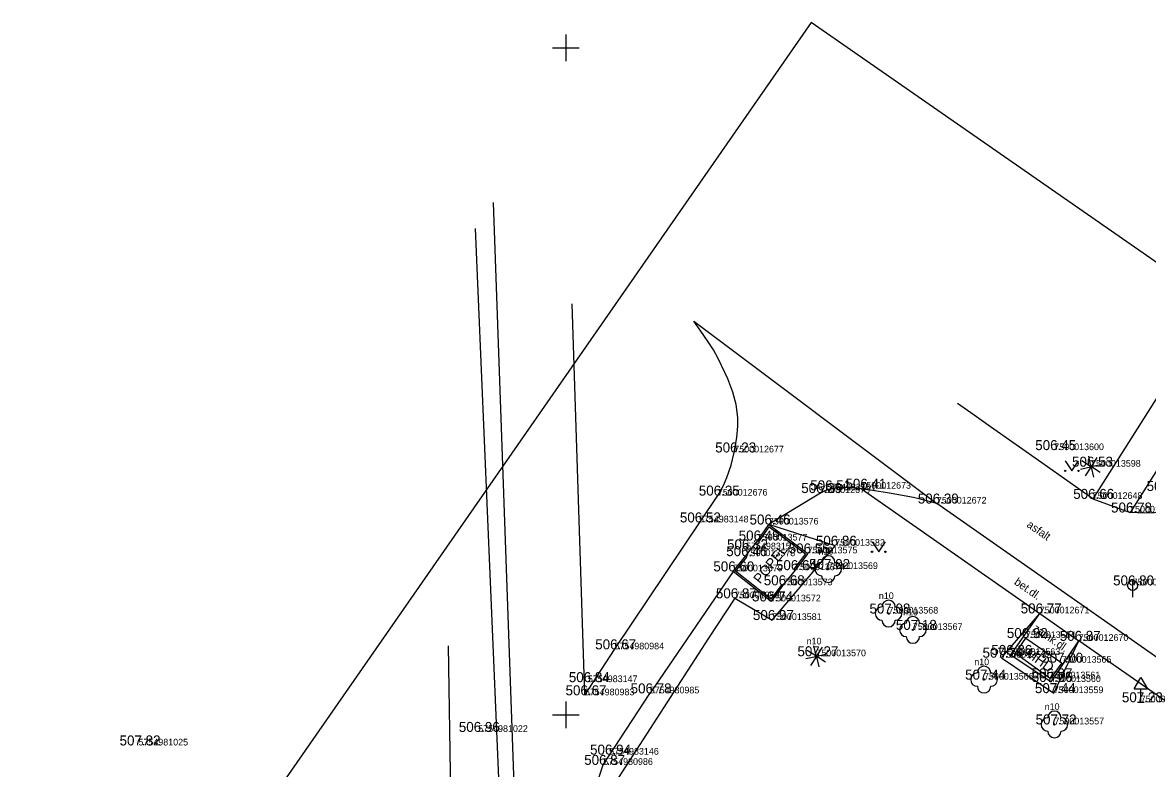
# Model space of a CAD drawing. Extents: x -669251 to -668549, y -1128351 to -1127698.
# Drawn here: x -669040.7 to -668956.4, y -1127754 to -1127698.1 of the extents above; entities that cross this region are included whole.
import ezdxf

# ---------------------------------------------------------------- set-up
doc = ezdxf.new("R2010")
doc.units = 0
for name, color, linetype in [('Vrstva 1', 7, 'Continuous'), ('Vrstva 10', 7, 'Continuous'), ('Vrstva 11', 7, 'Continuous'), ('Vrstva 14', 7, 'Continuous'), ('Vrstva 2', 7, 'Continuous'), ('Vrstva 22', 7, 'Continuous'), ('Vrstva 27', 7, 'Continuous'), ('Vrstva 3', 7, 'Continuous'), ('Vrstva 34', 7, 'Continuous'), ('Vrstva 36', 7, 'Continuous'), ('Vrstva 40', 7, 'Continuous'), ('Vrstva 42', 7, 'Continuous'), ('Vrstva 47', 7, 'Continuous'), ('Vrstva 5', 7, 'Continuous'), ('Vrstva 60', 7, 'Continuous'), ('Vrstva 61', 7, 'Continuous'), ('Vrstva 7', 7, 'Continuous')]:
    doc.layers.add(name, color=color, linetype=linetype)

msp = doc.modelspace()

# ---------------------------------------------------------------- linework, layer by layer
at = {"layer": 'Vrstva 1'}
for p, q in [((-668987.371, -1127730.338), (-668987.371, -1127730.338)), ((-668963.378, -1127730.163), (-668963.378, -1127730.163)), ((-668960.621, -1127731.406), (-668960.621, -1127731.406)), ((-668980.919, -1127733.381), (-668980.919, -1127733.381)), ((-668980.484, -1127733.176), (-668980.484, -1127733.176)), ((-668977.843, -1127733.058), (-668977.843, -1127733.058)), ((-668988.6, -1127733.573), (-668988.6, -1127733.573)), ((-668972.179, -1127734.169), (-668972.179, -1127734.169)), ((-668960.495, -1127733.821), (-668960.495, -1127733.821)), ((-668957.695, -1127734.841), (-668957.695, -1127734.841)), ((-668990.019, -1127735.584), (-668990.019, -1127735.584)), ((-668984.772, -1127735.741), (-668984.772, -1127735.741)), ((-668986.484, -1127737.608), (-668986.484, -1127737.608)), ((-668985.608, -1127736.94), (-668985.608, -1127736.94)), ((-668979.801, -1127737.333), (-668979.801, -1127737.333)), ((-668986.519, -1127738.114), (-668986.519, -1127738.114)), ((-668981.859, -1127737.906), (-668981.859, -1127737.906)), ((-668987.461, -1127739.256), (-668987.461, -1127739.256)), ((-668982.804, -1127739.163), (-668982.804, -1127739.163)), ((-668980.324, -1127739.079), (-668980.324, -1127739.079)), ((-668983.718, -1127740.297), (-668983.718, -1127740.297)), ((-668957.506, -1127740.307), (-668957.506, -1127740.307)), ((-668987.321, -1127741.273), (-668987.321, -1127741.273)), ((-668984.608, -1127741.507), (-668984.608, -1127741.507)), ((-668975.801, -1127742.415), (-668975.801, -1127742.415)), ((-668964.469, -1127742.407), (-668964.469, -1127742.407)), ((-668984.541, -1127742.903), (-668984.541, -1127742.903)), ((-668973.983, -1127743.642), (-668973.983, -1127743.642)), ((-668965.506, -1127744.254), (-668965.506, -1127744.254)), ((-668996.352, -1127745.1), (-668996.352, -1127745.1)), ((-668961.545, -1127744.464), (-668961.545, -1127744.464)), ((-668981.218, -1127745.619), (-668981.218, -1127745.619)), ((-668967.345, -1127745.727), (-668967.345, -1127745.727)), ((-668966.649, -1127745.52), (-668966.649, -1127745.52)), ((-668962.815, -1127746.103), (-668962.815, -1127746.103)), ((-668998.345, -1127747.56), (-668998.345, -1127747.56)), ((-668968.649, -1127747.373), (-668968.649, -1127747.373)), ((-668963.652, -1127747.276), (-668963.652, -1127747.276)), ((-668963.608, -1127747.547), (-668963.608, -1127747.547)), ((-668998.578, -1127748.546), (-668998.578, -1127748.546)), ((-668993.711, -1127748.403), (-668993.711, -1127748.403)), ((-668963.417, -1127748.384), (-668963.417, -1127748.384)), ((-668956.897, -1127749.069), (-668956.897, -1127749.069)), ((-668963.367, -1127750.731), (-668963.367, -1127750.731)), ((-669006.566, -1127751.293), (-669006.566, -1127751.293)), ((-669032.037, -1127752.307), (-669032.037, -1127752.307)), ((-668996.75, -1127752.993), (-668996.75, -1127752.993)), ((-668997.193, -1127753.764), (-668997.193, -1127753.764))]:
    msp.add_line(p, q, dxfattribs=at)
at = {"layer": 'Vrstva 10'}
for p, q in [((-669003.824, -1127756.515), (-669005.418, -1127711.59)), ((-668947.975, -1127714.013), (-668960.495, -1127733.821)), ((-668946.997, -1127717.845), (-668957.695, -1127734.841)), ((-668998.578, -1127748.546), (-668999.53, -1127719.204)), ((-668977.843, -1127733.058), (-668964.469, -1127742.407)), ((-668986.519, -1127738.114), (-668985.608, -1127736.94)), ((-668987.461, -1127739.256), (-668993.711, -1127748.403)), ((-668982.804, -1127739.163), (-668983.718, -1127740.297)), ((-668966.649, -1127745.52), (-668964.469, -1127742.407)), ((-668998.578, -1127748.546), (-668996.352, -1127745.1)), ((-668963.608, -1127747.547), (-668961.545, -1127744.464)), ((-668934.08, -1127763.578), (-668961.545, -1127744.464)), ((-668966.649, -1127745.52), (-668963.608, -1127747.547)), ((-668997.193, -1127753.764), (-668993.711, -1127748.403)), ((-668997.972, -1127756.059), (-668997.193, -1127753.764))]:
    msp.add_line(p, q, dxfattribs=at)
for points in [[(-668996.352, -1127745.1), (-668992.476, -1127739.336), (-668988.6, -1127733.573), (-668988.174, -1127732.821), (-668987.919, -1127732.22), (-668987.615, -1127731.285), (-668987.371, -1127730.338), (-668987.169, -1127729.22), (-668987.105, -1127728.36), (-668987.113, -1127727.713), (-668987.227, -1127726.753), (-668987.476, -1127725.824), (-668987.862, -1127724.813), (-668988.543, -1127723.35), (-668988.938, -1127722.65), (-668989.374, -1127721.974), (-668989.884, -1127721.236), (-668990.394, -1127720.498)], [(-668943.828, -1127723.016), (-668947.216, -1127727.392), (-668950.604, -1127731.768), (-668951.311, -1127732.58), (-668951.902, -1127733.131), (-668952.38, -1127733.508), (-668953.156, -1127734.01), (-668954.004, -1127734.43), (-668954.644, -1127734.658), (-668955.127, -1127734.774), (-668955.856, -1127734.87), (-668956.592, -1127734.881), (-668957.144, -1127734.861), (-668957.695, -1127734.841)], [(-668960.495, -1127733.821), (-668964.324, -1127731.119), (-668968.152, -1127728.415), (-668969.393, -1127727.536), (-668970.634, -1127726.657)], [(-668972.179, -1127734.169), (-668972.659, -1127734.039), (-668973.942, -1127733.727), (-668975.89, -1127733.357), (-668977.843, -1127733.058), (-668978.628, -1127732.971), (-668979.231, -1127732.955), (-668979.68, -1127732.984), (-668980.327, -1127733.116), (-668980.631, -1127733.23), (-668980.919, -1127733.381), (-668982.846, -1127734.561), (-668984.772, -1127735.741)], [(-668947.059, -1127751.764), (-668959.619, -1127742.966), (-668972.179, -1127734.169)]]:
    msp.add_lwpolyline(points, dxfattribs=at)
at = {"layer": 'Vrstva 11'}
for p, q in [((-668990.394, -1127720.498), (-668972.179, -1127734.169)), ((-668960.495, -1127733.821), (-668957.695, -1127734.841)), ((-668964.469, -1127742.407), (-668961.545, -1127744.464))]:
    msp.add_line(p, q, dxfattribs=at)
at = {"layer": 'Vrstva 14'}
for p, q in [((-669006.806, -1127713.552), (-669004.988, -1127756.361)), ((-668979.801, -1127737.333), (-668984.772, -1127735.741)), ((-668984.541, -1127742.903), (-668979.801, -1127737.333)), ((-668987.321, -1127741.273), (-668989.294, -1127744.271)), ((-668987.321, -1127741.273), (-668984.541, -1127742.903)), ((-668967.345, -1127745.727), (-668964.469, -1127742.407)), ((-668989.294, -1127744.271), (-668996.266, -1127755.056)), ((-669008.429, -1127768.237), (-669008.802, -1127744.83)), ((-668963.417, -1127748.384), (-668961.545, -1127744.464)), ((-668967.345, -1127745.727), (-668963.417, -1127748.384))]:
    msp.add_line(p, q, dxfattribs=at)
at = {"layer": 'Vrstva 22'}
for p, q in [((-668960.629, -1127731.366), (-668960.801, -1127730.612)), ((-668960.187, -1127730.716), (-668960.601, -1127731.372)), ((-668961.415, -1127731.586), (-668960.661, -1127731.414)), ((-668960.655, -1127731.386), (-668961.311, -1127730.972)), ((-668960.641, -1127731.44), (-668961.055, -1127732.096)), ((-668960.613, -1127731.446), (-668960.441, -1127732.2)), ((-668959.931, -1127731.84), (-668960.587, -1127731.426)), ((-668960.581, -1127731.398), (-668959.827, -1127731.226)), ((-668981.252, -1127745.599), (-668981.908, -1127745.185)), ((-668981.226, -1127745.579), (-668981.398, -1127744.825)), ((-668980.784, -1127744.929), (-668981.198, -1127745.585)), ((-668982.012, -1127745.799), (-668981.258, -1127745.627)), ((-668981.238, -1127745.653), (-668981.652, -1127746.309)), ((-668981.21, -1127745.659), (-668981.038, -1127746.413)), ((-668980.528, -1127746.053), (-668981.184, -1127745.639)), ((-668981.178, -1127745.611), (-668980.424, -1127745.439))]:
    msp.add_line(p, q, dxfattribs=at)
for centre, radius in [((-668960.621, -1127731.406), 0.04), ((-668980.324, -1127739.079), 0.05), ((-668975.801, -1127742.415), 0.05), ((-668973.983, -1127743.642), 0.05), ((-668981.218, -1127745.619), 0.04), ((-668968.649, -1127747.373), 0.05), ((-668963.367, -1127750.731), 0.05)]:
    msp.add_circle(centre, radius, dxfattribs=at)
for centre, start, end in [((-668980.324, -1127738.579), 0, 180), ((-668980.824, -1127739.079), 90, 270), ((-668979.824, -1127739.079), 270, 90), ((-668980.324, -1127739.579), 180, 0), ((-668975.801, -1127741.915), 0, 180), ((-668976.301, -1127742.415), 90, 270), ((-668975.301, -1127742.415), 270, 90), ((-668973.983, -1127743.142), 0, 180), ((-668975.801, -1127742.915), 180, 0), ((-668974.483, -1127743.642), 90, 270), ((-668973.483, -1127743.642), 270, 90), ((-668973.983, -1127744.142), 180, 0), ((-668969.149, -1127747.373), 90, 270), ((-668968.649, -1127746.873), 0, 180), ((-668968.149, -1127747.373), 270, 90), ((-668968.649, -1127747.873), 180, 0), ((-668963.867, -1127750.731), 90, 270), ((-668963.367, -1127750.231), 0, 180), ((-668962.867, -1127750.731), 270, 90), ((-668963.367, -1127751.231), 180, 0)]:
    msp.add_arc(centre, 0.5, start, end, dxfattribs=at)
at = {"layer": 'Vrstva 27'}
msp.add_line((-668957.506, -1127739.932), (-668957.506, -1127741.182), dxfattribs=at)
msp.add_circle((-668957.506, -1127740.307), 0.375, dxfattribs=at)
at = {"layer": 'Vrstva 34'}
for p, q in [((-668957.397, -1127748.069), (-668956.897, -1127747.219)), ((-668956.897, -1127747.219), (-668956.397, -1127748.069)), ((-668957.397, -1127748.069), (-668956.397, -1127748.069)), ((-668956.897, -1127749.069), (-668956.897, -1127748.069)), ((-668957.147, -1127749.069), (-668956.647, -1127749.069))]:
    msp.add_line(p, q, dxfattribs=at)
at = {"layer": 'Vrstva 36'}
for p, q in [((-668962.564, -1127730.974), (-668962.064, -1127731.724)), ((-668962.064, -1127731.724), (-668961.564, -1127730.974)), ((-668977.041, -1127737.033), (-668976.541, -1127737.783)), ((-668976.541, -1127737.783), (-668976.041, -1127737.033))]:
    msp.add_line(p, q, dxfattribs=at)
for centre in [(-668962.566, -1127731.724), (-668961.566, -1127731.724), (-668977.041, -1127737.783), (-668976.041, -1127737.783)]:
    msp.add_circle(centre, 0.05, dxfattribs=at)
at = {"layer": 'Vrstva 5'}
for p, q in [((-668966.289, -1127745.394), (-668965.506, -1127744.254)), ((-668965.506, -1127744.254), (-668962.815, -1127746.103)), ((-668966.289, -1127745.394), (-668963.652, -1127747.276)), ((-668962.815, -1127746.103), (-668963.652, -1127747.276))]:
    msp.add_line(p, q, dxfattribs=at)
at = {"layer": 'Vrstva 60'}
msp.add_lwpolyline([(-668982.815, -1128190.464), (-668751.689, -1127857.889), (-668981.618, -1127698.099), (-669212.743, -1128030.674)], close=True, dxfattribs=at)
at = {"layer": 'Vrstva 61'}
for p, q in [((-669000, -1127699), (-669000, -1127701)), ((-669001, -1127700), (-668999, -1127700)), ((-669000, -1127749), (-669000, -1127751)), ((-669001, -1127750), (-668999, -1127750))]:
    msp.add_line(p, q, dxfattribs=at)
at = {"layer": 'Vrstva 7'}
for p, q in [((-668985.608, -1127736.94), (-668984.772, -1127735.741)), ((-668985.51, -1127737.009), (-668984.744, -1127735.911)), ((-668984.772, -1127735.741), (-668981.859, -1127737.906)), ((-668984.744, -1127735.911), (-668982.027, -1127737.93)), ((-668985.608, -1127736.94), (-668985.51, -1127737.009)), ((-668987.461, -1127739.256), (-668986.519, -1127738.114)), ((-668987.29, -1127739.238), (-668986.426, -1127738.19)), ((-668986.426, -1127738.19), (-668986.519, -1127738.114)), ((-668982.027, -1127737.93), (-668982.9, -1127739.091)), ((-668981.859, -1127737.906), (-668982.804, -1127739.163)), ((-668984.608, -1127741.507), (-668987.461, -1127739.256)), ((-668984.631, -1127741.336), (-668987.29, -1127739.238)), ((-668982.9, -1127739.091), (-668982.804, -1127739.163)), ((-668983.815, -1127740.226), (-668984.631, -1127741.336)), ((-668983.718, -1127740.297), (-668984.608, -1127741.507)), ((-668983.718, -1127740.297), (-668983.815, -1127740.226))]:
    msp.add_line(p, q, dxfattribs=at)

# ---------------------------------------------------------------- texts
at = {"layer": 'Vrstva 2'}
for s, p in [('7500012677', (-668987.371, -1127730.338)), ('7500013600', (-668963.378, -1127730.163)), ('7500013598', (-668960.621, -1127731.406)), ('7500012673', (-668977.843, -1127733.058)), ('7500012676', (-668988.6, -1127733.573)), ('7500012675', (-668980.919, -1127733.381)), ('5754983151', (-668980.484, -1127733.176)), ('7500012648', (-668960.495, -1127733.821)), ('7500012672', (-668972.179, -1127734.169)), ('5754983148', (-668990.019, -1127735.584)), ('7500012649', (-668957.695, -1127734.841)), ('7500013576', (-668984.772, -1127735.741)), ('7500013577', (-668985.608, -1127736.94)), ('7500013578', (-668986.519, -1127738.114)), ('5754983152', (-668986.484, -1127737.608)), ('7500013575', (-668981.859, -1127737.906)), ('7500013582', (-668979.801, -1127737.333)), ('7500013579', (-668987.461, -1127739.256)), ('7500013574', (-668982.804, -1127739.163)), ('7500013569', (-668980.324, -1127739.079)), ('7500013573', (-668983.718, -1127740.297)), ('7500013621', (-668957.506, -1127740.307)), ('7500013580', (-668987.321, -1127741.273)), ('7500013572', (-668984.608, -1127741.507)), ('7500013581', (-668984.541, -1127742.903)), ('7500013568', (-668975.801, -1127742.415)), ('7500012671', (-668964.469, -1127742.407)), ('7500013567', (-668973.983, -1127743.642)), ('7500013564', (-668965.506, -1127744.254)), ('7500012670', (-668961.545, -1127744.464)), ('5754980984', (-668996.352, -1127745.1)), ('7500013570', (-668981.218, -1127745.619)), ('7500013562', (-668967.345, -1127745.727)), ('7500013563', (-668966.649, -1127745.52)), ('7500013565', (-668962.815, -1127746.103)), ('7500013566', (-668968.649, -1127747.373)), ('7500013561', (-668963.652, -1127747.276)), ('5754983147', (-668998.345, -1127747.56)), ('7500013560', (-668963.608, -1127747.547)), ('5754980983', (-668998.578, -1127748.546)), ('5754980985', (-668993.711, -1127748.403)), ('7500013559', (-668963.417, -1127748.384)), ('7500013558', (-668956.897, -1127749.069)), ('7500013557', (-668963.367, -1127750.731)), ('5754981022', (-669006.566, -1127751.293)), ('5754981025', (-669032.037, -1127752.307)), ('5754983146', (-668996.75, -1127752.993)), ('5754980986', (-668997.193, -1127753.764))]:
    msp.add_text(s, height=0.5, dxfattribs=at).set_placement(p)
at = {"layer": 'Vrstva 3'}
for s, p in [('506.23 ', (-668988.8, -1127730.338)), ('506.45 ', (-668964.807, -1127730.163)), ('506.53 ', (-668962.05, -1127731.406)), ('506.51 ', (-668981.676, -1127733.176)), ('506.41 ', (-668979.035, -1127733.058)), ('506.70 ', (-668956.456, -1127733.226)), ('506.35 ', (-668990.029, -1127733.573)), ('506.39 ', (-668982.351, -1127733.381)), ('506.39 ', (-668973.611, -1127734.169)), ('506.66 ', (-668961.961, -1127733.821)), ('506.78 ', (-668959.124, -1127734.841)), ('506.52 ', (-668991.448, -1127735.584)), ('506.46 ', (-668986.224, -1127735.741)), ('506.49 ', (-668987.04, -1127736.94)), ('506.86 ', (-668981.253, -1127737.333)), ('506.46 ', (-668987.971, -1127738.114)), ('506.32 ', (-668987.913, -1127737.608)), ('506.55 ', (-668983.288, -1127737.906)), ('506.64 ', (-668984.246, -1127739.163)), ('507.02 ', (-668981.76, -1127739.079)), ('506.60 ', (-668988.939, -1127739.256)), ('506.68 ', (-668985.16, -1127740.297)), ('506.80 ', (-668958.97, -1127740.307)), ('506.87 ', (-668988.75, -1127741.273)), ('506.74 ', (-668986.037, -1127741.507)), ('507.08 ', (-668977.237, -1127742.415)), ('506.77 ', (-668965.898, -1127742.407)), ('506.97 ', (-668985.972, -1127742.903)), ('507.18 ', (-668975.257, -1127743.642)), ('506.92 ', (-668966.937, -1127744.254)), ('506.67 ', (-668997.794, -1127745.1)), ('506.87 ', (-668962.974, -1127744.464)), ('507.27 ', (-668982.633, -1127745.619)), ('507.34 ', (-668968.76, -1127745.727)), ('506.86 ', (-668968.101, -1127745.52)), ('507.00 ', (-668964.287, -1127746.103)), ('506.84 ', (-668999.774, -1127747.56)), ('507.44 ', (-668970.064, -1127747.373)), ('506.97 ', (-668965.083, -1127747.276)), ('507.06 ', (-668965.068, -1127747.547)), ('506.78 ', (-668995.14, -1127748.403)), ('507.44 ', (-668964.832, -1127748.384)), ('506.67 ', (-669000.02, -1127748.546)), ('507.23 ', (-668958.312, -1127749.069)), ('507.72 ', (-668964.782, -1127750.731)), ('506.96 ', (-669008.02, -1127751.293)), ('507.82 ', (-669033.452, -1127752.307)), ('506.94 ', (-668998.181, -1127752.993)), ('506.87 ', (-668998.622, -1127753.764))]:
    msp.add_text(s, height=0.75, dxfattribs=at).set_placement(p)
at = {"layer": 'Vrstva 40'}
for s, rotation, p in [('asfalt', 325.38469, (-668965.497, -1127735.878)), ('bet.dl.', 325.0448, (-668966.439, -1127740.175)), ('zamk.dl.', 325.50684, (-668965.046, -1127743.647))]:
    msp.add_text(s, height=0.6, rotation=rotation, dxfattribs=at).set_placement(p)
at = {"layer": 'Vrstva 42'}
for s, rotation, p in [('POPEL.', 51.13131, (-668985.421, -1127740.245)), ('MHD', 324.49006, (-668965.601, -1127745.542))]:
    msp.add_text(s, height=0.75, rotation=rotation, dxfattribs=at).set_placement(p)
at = {"layer": 'Vrstva 47'}
for height, p in [(0.499, (-668981.054, -1127737.993)), (0.499, (-668976.531, -1127741.329)), (0.499, (-668974.713, -1127742.556)), (0.5, (-668981.948, -1127744.733)), (0.499, (-668969.379, -1127746.287)), (0.499, (-668964.097, -1127749.645))]:
    msp.add_text('n10', height=height, dxfattribs=at).set_placement(p)

doc.saveas('drawing.dxf')
